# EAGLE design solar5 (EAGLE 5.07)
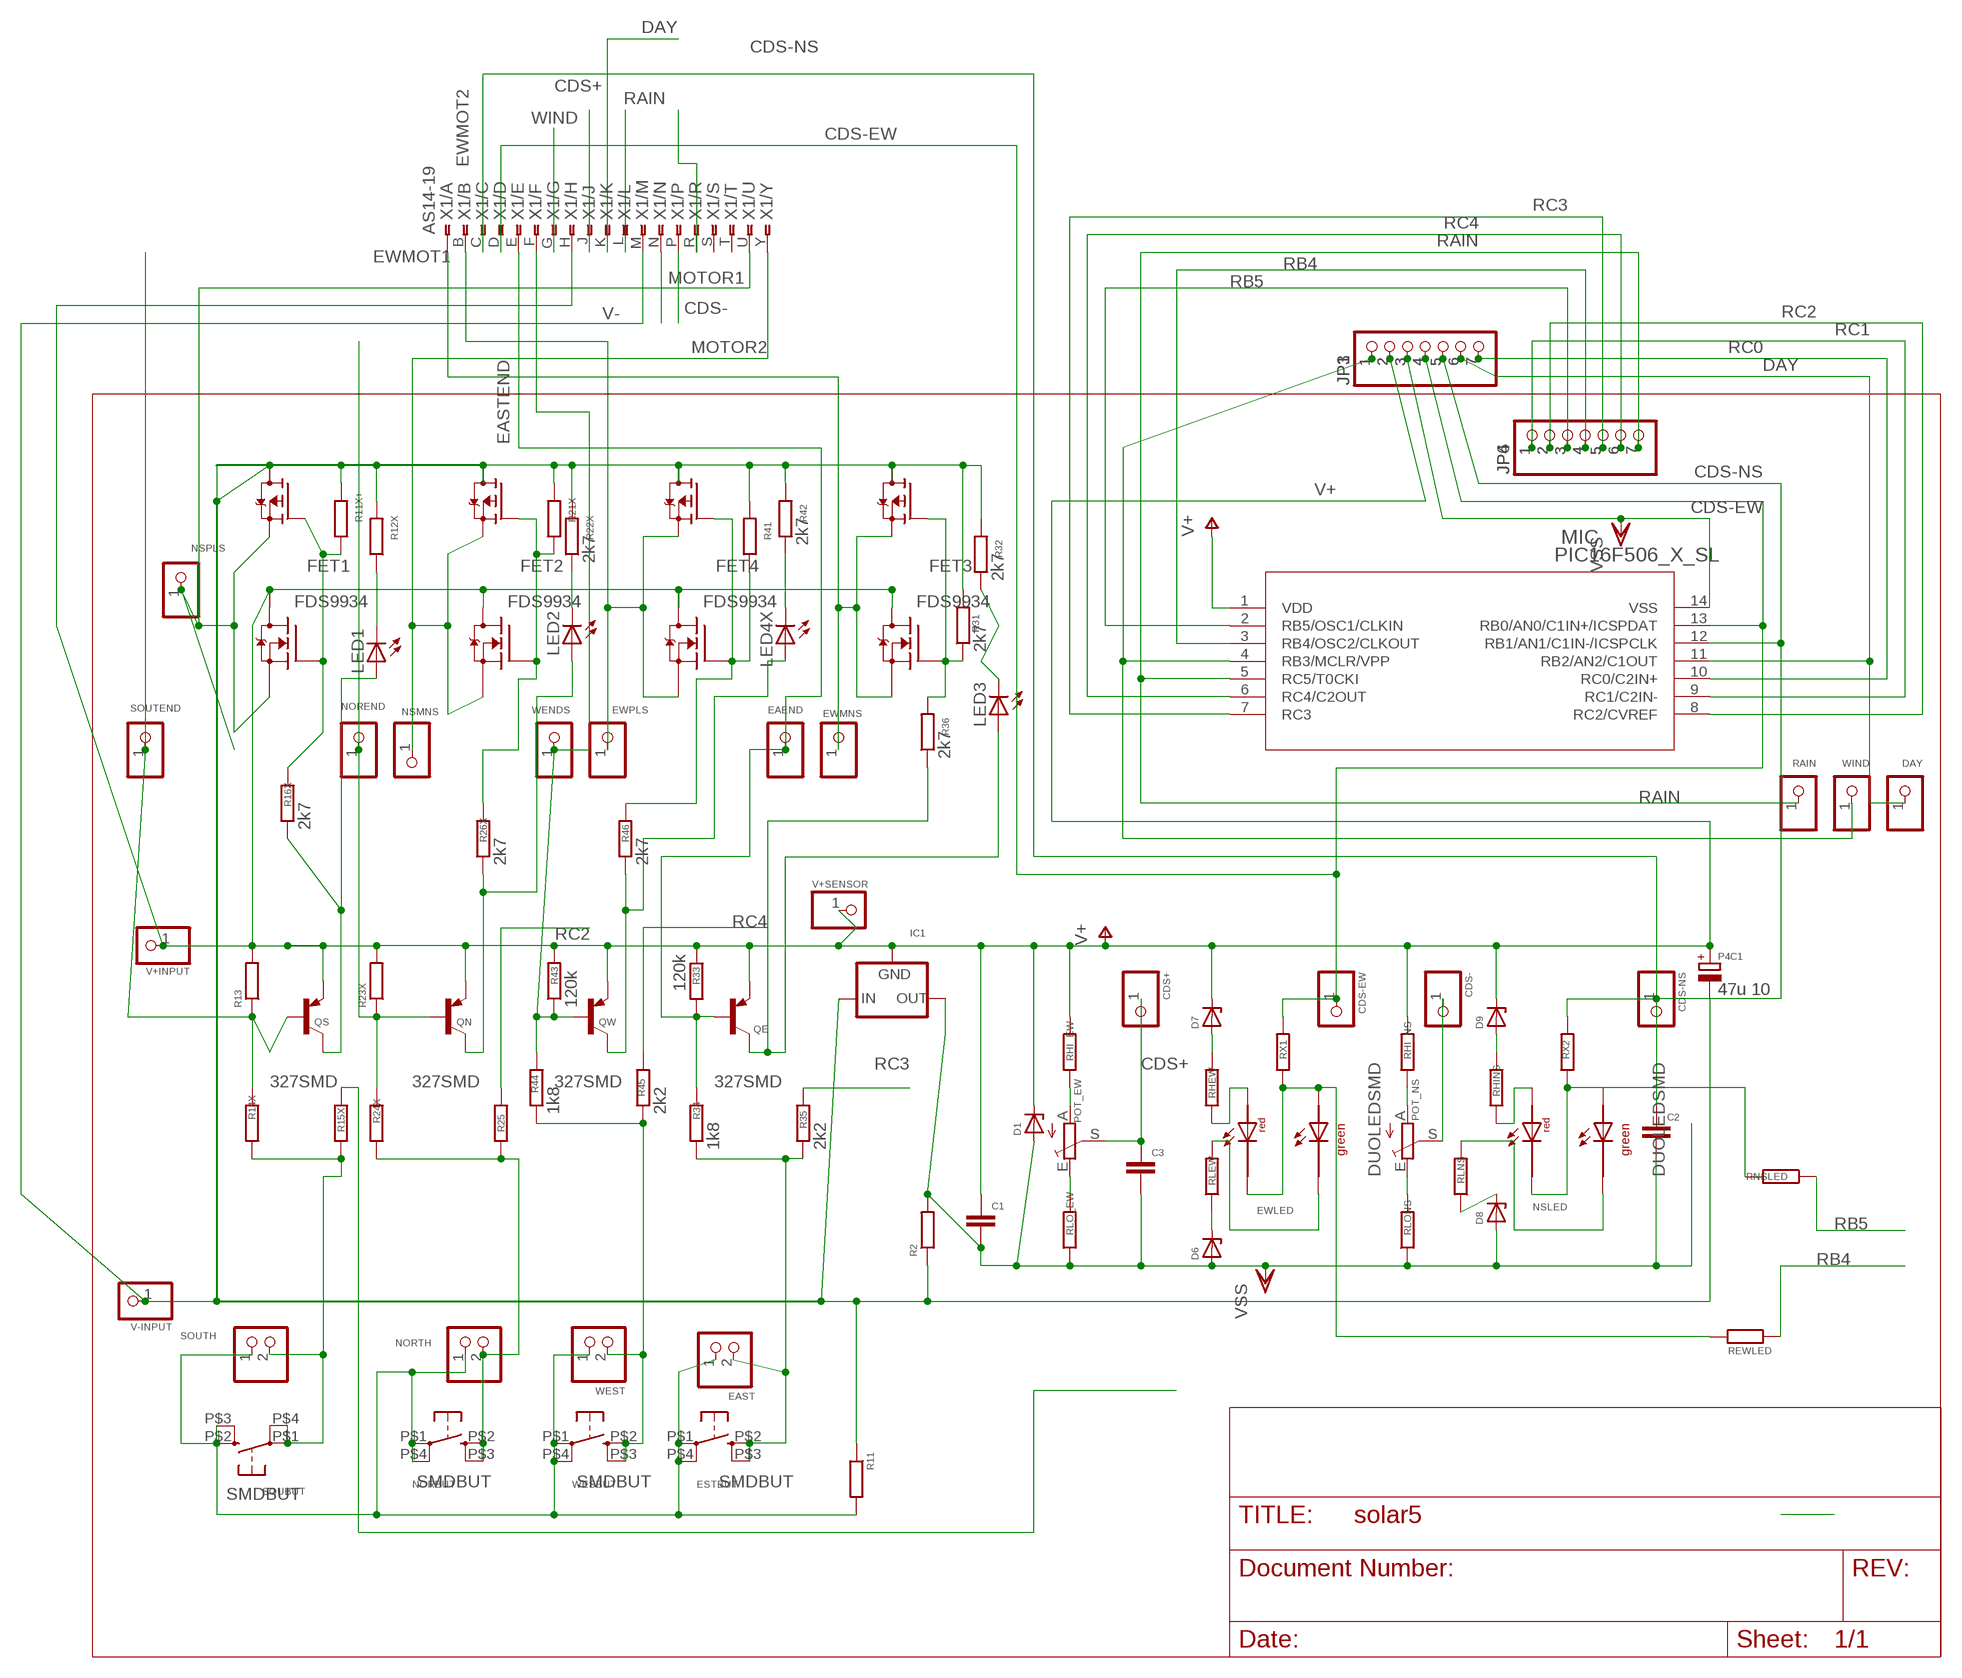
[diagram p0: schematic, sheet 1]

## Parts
C1  C-EUC1206  [C1206]
C2  C-EUC1206  [C1206]
C3  C-EUC1206  [C1206]
CDS+  PINHD-1X1INCH  [1X01]
CDS-  PINHD-1X1INCH  [1X01]
CDS-EW  PINHD-1X1INCH  [1X01]
CDS-NS  PINHD-1X1INCH  [1X01]
D1  ZENER-DIODESOD80C  [SOD80C]
D6  ZENER-DIODESOD80C  [SOD80C]
D7  ZENER-DIODESOD80C  [SOD80C]
D8  ZENER-DIODESOD80C  [SOD80C]
D9  ZENER-DIODESOD80C  [SOD80C]
DAY  PINHD-1X1INCH  [1X01]
EAEND  PINHD-1X1INCH  [1X01]
EAST  PINHD-1X2STR  [1X02]
ESTBUT  SMDBUT  [SMD10/5]
EWLED  DUOLEDSMD  [DUOLEDSMD]
EWMNS  PINHD-1X10MM6  [1X01M]
EWPLS  PINHD-1X10MM6  [1X01M]
FET1  FDS9934  [SO-8]
FET2  FDS9934  [SO-8]
FET3  FDS9934  [SO-8]
FET4  FDS9934  [SO-8]
IC1  79LXX  [79LXX]
JP1  PINHD-1X7  [1X07]
JP3  PINHD-1X7  [1X07]
JP4  PINHD-1X7  [1X07]
JP6  PINHD-1X7  [1X07]
LED1  LEDCHIPLED_1206  [CHIPLED_1206]
LED2  LEDCHIPLED_1206  [CHIPLED_1206]
LED3  LEDCHIPLED_1206  [CHIPLED_1206]
LED4X  LEDCHIPLED_1206  [CHIPLED_1206]
MIC  PIC16F506_X_SL  [SOIC14_N_MC]
NORBUT  SMDBUT  [SMD10/5]
NOREND  PINHD-1X1INCH  [1X01]
NORTH  PINHD-1X2STR  [1X02]
NSLED  DUOLEDSMD  [DUOLEDSMD]
NSMNS  PINHD-1X1INCH  [1X01]
NSPLS  PINHD-1X10MM6  [1X01M]
P4C1  47u 10  CPOL-EUE5-8.5  [E5-8,5]
POT_EW  TRIM_EU-CA6V  [CA6V]
POT_NS  TRIM_EU-CA6V  [CA6V]
QE  327SMD  BC327SMD  [SOT23-BEC]
QN  327SMD  BC327SMD  [SOT23-BEC]
QS  327SMD  BC327SMD  [SOT23-BEC]
QW  327SMD  BC327SMD  [SOT23-BEC]
R2  R-EU_R0805  [R0805]
R11  R-EU_R0805  [R0805]
R11X+  R-EU_R0805  [R0805]
R12X  R-EU_R0805  [R0805]
R13  R-EU_R0805  [R0805]
R14X  R-EU_R1206  [R1206]
R15X  R-EU_R0805  [R0805]
R16X  2k7  R-EU_R0805  [R0805]
R21X  R-EU_R0805  [R0805]
R22X  2k7  R-EU_R0805  [R0805]
R23X  R-EU_R1206  [R1206]
R24X  R-EU_R1206  [R1206]
R25  R-EU_R0805  [R0805]
R26X  2k7  R-EU_R0805  [R0805]
R31  2k7  R-EU_R0805  [R0805]
R32  2k7  R-EU_R0805  [R0805]
R33  120k  R-EU_R0805  [R0805]
R34  1k8  R-EU_R0805  [R0805]
R35  2k2  R-EU_R0805  [R0805]
R36  2k7  R-EU_R0805  [R0805]
R41  R-EU_R0805  [R0805]
R42  2k7  R-EU_R0805  [R0805]
R43  120k  R-EU_R0805  [R0805]
R44  1k8  R-EU_R0805  [R0805]
R45  2k2  R-EU_R0805  [R0805]
R46  2k7  R-EU_R0805  [R0805]
RAIN  PINHD-1X1INCH  [1X01]
REWLED  R-EU_R0805  [R0805]
RHEW  R-EU_R1206  [R1206]
RHI_EW  R-EU_R1206  [R1206]
RHI_NS  R-EU_R1206  [R1206]
RHINS  R-EU_R1206  [R1206]
RLEW  R-EU_R1206  [R1206]
RLNS  R-EU_R1206  [R1206]
RLO_EW  R-EU_R1206  [R1206]
RLONS  R-EU_R0805  [R0805]
RNSLED  R-EU_R0805  [R0805]
RX1  R-EU_R0805  [R0805]
RX2  R-EU_R0805  [R0805]
SOUBUT  SMDBUT  [SMD10/5]
SOUTEND  PINHD-1X1INCH  [1X01]
SOUTH  PINHD-1X2STR  [1X02]
V+INPUT  PINHD-1X1INCH  [1X01]
V+SENSOR  PINHD-1X10MM6  [1X01M]
V-INPUT  PINHD-1X10MM6  [1X01M]
WENDS  PINHD-1X1INCH  [1X01]
WESBUT  SMDBUT  [SMD10/5]
WEST  PINHD-1X2STR  [1X02]
WIND  PINHD-1X1INCH  [1X01]
X1  AS14-19  AS14-19OLIVE  [Y28M-19TK]

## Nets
CDS+: C3.1 CDS+.1 POT_EW.S X1.J
CDS-: CDS-.1 POT_NS.S X1.P
CDS-EW: CDS-EW.1 JP1.4 JP3.4 MIC.13(RB0/AN0/C1IN+/ICSPDAT) RX1.2 X1.D
CDS-NS: C2.1 CDS-NS.1 JP1.5 JP3.5 MIC.12(RB1/AN1/C1IN-/ICSPCLK) RX2.2 X1.C
DAY: DAY.1 JP1.6 JP3.6 MIC.11(RB2/AN2/C1OUT) X1.K
EASTEND: EAEND.1 QE.B R33.2 R34.2 X1.E
EWMOT1: EWMNS.1 FET3.1(Q1S) FET3.3(Q2S) X1.A
EWMOT2: EWPLS.1 FET4.1(Q1S) FET4.3(Q2S) X1.B
MOTOR1: FET1.1(Q1S) FET1.3(Q2S) NSPLS.1 X1.U
MOTOR2: FET2.1(Q1S) FET2.3(Q2S) NSMNS.1 X1.Y
N$1: POT_NS.E RLONS.2
N$2: LED1.A QS.C R16X.1
N$3: LED2.A QN.C R26X.1
N$4: FET2.2(Q1G) FET2.4(Q2G) R21X.1 R26X.2
N$5: LED1.C R12X.1
N$6: EWLED.AGRN EWLED.CRED REWLED.2 RX1.1
N$8: LED2.C R22X.1
N$9: R14X.1 R15X.1 SOUBUT.P$1(P) SOUBUT.P$4(P1) SOUTH.2
N$10: LED4X.A QW.C R46.1
N$11: EAST.2 ESTBUT.P$2(S) ESTBUT.P$3(S1) R34.1 R35.1
N$14: D7.A RHEW.2
N$15: LED4X.C R42.1
N$17: NORBUT.P$2(S) NORBUT.P$3(S1) NORTH.2 R24X.1 R25.1
N$18: POT_NS.A RHI_NS.1
N$21: POT_EW.E RLO_EW.2
N$22: POT_EW.A RHI_EW.1
N$25: EWLED.ARED RHEW.1
N$27: D6.C RLEW.1
N$28: EWLED.CGRN RLEW.2
N$29: EAST.1 ESTBUT.P$1(P) ESTBUT.P$4(P1) NORBUT.P$1(P) NORBUT.P$4(P1) NORTH.1 R11.2 SOUBUT.P$2(S) SOUBUT.P$3(S1) SOUTH.1 WESBUT.P$1(P) WESBUT.P$4(P1) WEST.1
N$30: NSLED.AGRN NSLED.CRED RNSLED.2 RX2.1
N$37: LED3.A QE.C R36.1
N$39: R44.1 R45.1 WESBUT.P$2(S) WESBUT.P$3(S1) WEST.2
N$41: D9.A RHINS.2
N$42: NSLED.ARED RHINS.1
N$43: D8.C RLNS.1
N$44: NSLED.CGRN RLNS.2
N$50: FET1.2(Q1G) FET1.4(Q2G) R11X+.1 R16X.2
N$54: FET4.2(Q1G) FET4.4(Q2G) R41.1 R46.2
N$55: FET3.2(Q1G) FET3.4(Q2G) R31.1 R36.2
N$56: LED3.C R32.1
NOREND: NOREND.1 QN.B R23X.1 R24X.2 X1.N
RAIN: JP4.7 JP6.7 MIC.5(RC5/T0CKI) RAIN.1 X1.L
RB4: JP4.4 JP6.4 MIC.3(RB4/OSC2/CLKOUT) REWLED.1
RB5: JP4.3 JP6.3 MIC.2(RB5/OSC1/CLKIN) RNSLED.1
RC0: JP1.7 JP3.7 MIC.10(RC0/C2IN+)
RC1: JP4.1 JP6.1 MIC.9(RC1/C2IN-) R15X.2
RC2: JP4.2 JP6.2 MIC.8(RC2/CVREF) R25.2
RC3: JP4.5 JP6.5 MIC.7(RC3) R35.2
RC4: JP4.6 JP6.6 MIC.6(RC4/C2OUT) R45.2
SOU_END: QS.B R13.1 R14X.2 SOUTEND.1 X1.R
V+: C1.1 D1.C D7.C D9.C FET1.7(Q1D2) FET1.8(Q1D1) FET2.7(Q1D2) FET2.8(Q1D1) FET3.7(Q1D2) FET3.8(Q1D1) FET4.7(Q1D2) FET4.8(Q1D1) IC1.GND JP1.2 JP3.2 MIC.1(VDD) P4C1.+ QE.E QN.E QS.E QW.E R13.2 R23X.2 R33.1 R43.2 RHI_EW.2 RHI_NS.2 V+INPUT.1 V+SENSOR.1 X1.H
V-: FET1.5(Q2D2) FET1.6(Q2D) FET2.5(Q2D2) FET2.6(Q2D) FET3.5(Q2D2) FET3.6(Q2D) FET4.5(Q2D2) FET4.6(Q2D) IC1.IN P4C1.- R2.1 R11.1 R11X+.2 R12X.2 R21X.2 R22X.2 R31.2 R32.2 R41.2 R42.2 V-INPUT.1 X1.M
VSS: C1.2 C2.2 C3.2 D1.A D6.A D8.A IC1.OUT JP1.3 JP3.3 MIC.14(VSS) R2.2 RLO_EW.1 RLONS.1
WESTEND: QW.B R43.1 R44.2 WENDS.1 X1.F
WIND: JP1.1 JP3.1 MIC.4(RB3/MCLR/VPP) WIND.1 X1.G
Unconnected: X1.S X1.T

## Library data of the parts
C1-C3 = rcl-2:C-EU: CAPACITOR, European symbol
CDS+ CDS- CDS-EW CDS-NS DAY EAEND EWMNS EWPLS NOREND NSMNS NSPLS RAIN SOUTEND V+INPUT V+SENSOR V-INPUT WENDS WIND = pinhead(2):PINHD-1X1: PIN HEADER
D1 D6-D9 = diode-1:ZENER-DIODE: Z-Diode
EAST NORTH SOUTH WEST = pinhead:PINHD-1X2: PIN HEADER
ESTBUT NORBUT SOUBUT WESBUT = switch-omron:SMDBUT
EWLED NSLED = led:DUOLEDSMD
FET1-FET4 = transistor-fet:FDS9934
IC1 = v-reg:79LXX: VOLTAGE REGULATOR
JP1 JP3 JP4 JP6 = pinhead:PINHD-1X7: PIN HEADER
LED1-LED3 LED4X = led:LED: LED
MIC = pic16f506mc:PIC16F506_X_SL
P4C1 = rcl:CPOL-EU: POLARIZED CAPACITOR, European symbol
POT_EW POT_NS = pot:TRIM_EU-: POTENTIOMETER
QE QN QS QW = transistor-pnp:BC327*: PNP Transistror
R2 R11 R11X+ R12X R13 R14X R15X R16X R21X R22X R23X R24X R25 R26X R31-R36 R41-R46 REWLED RHEW RHI_EW RHI_NS RHINS RLEW RLNS RLO_EW RLONS RNSLED RX1 RX2 = rcl-2:R-EU_: RESISTOR, European symbol
X1 = con-deutsch:AS14-19: DEUTSCH Connector

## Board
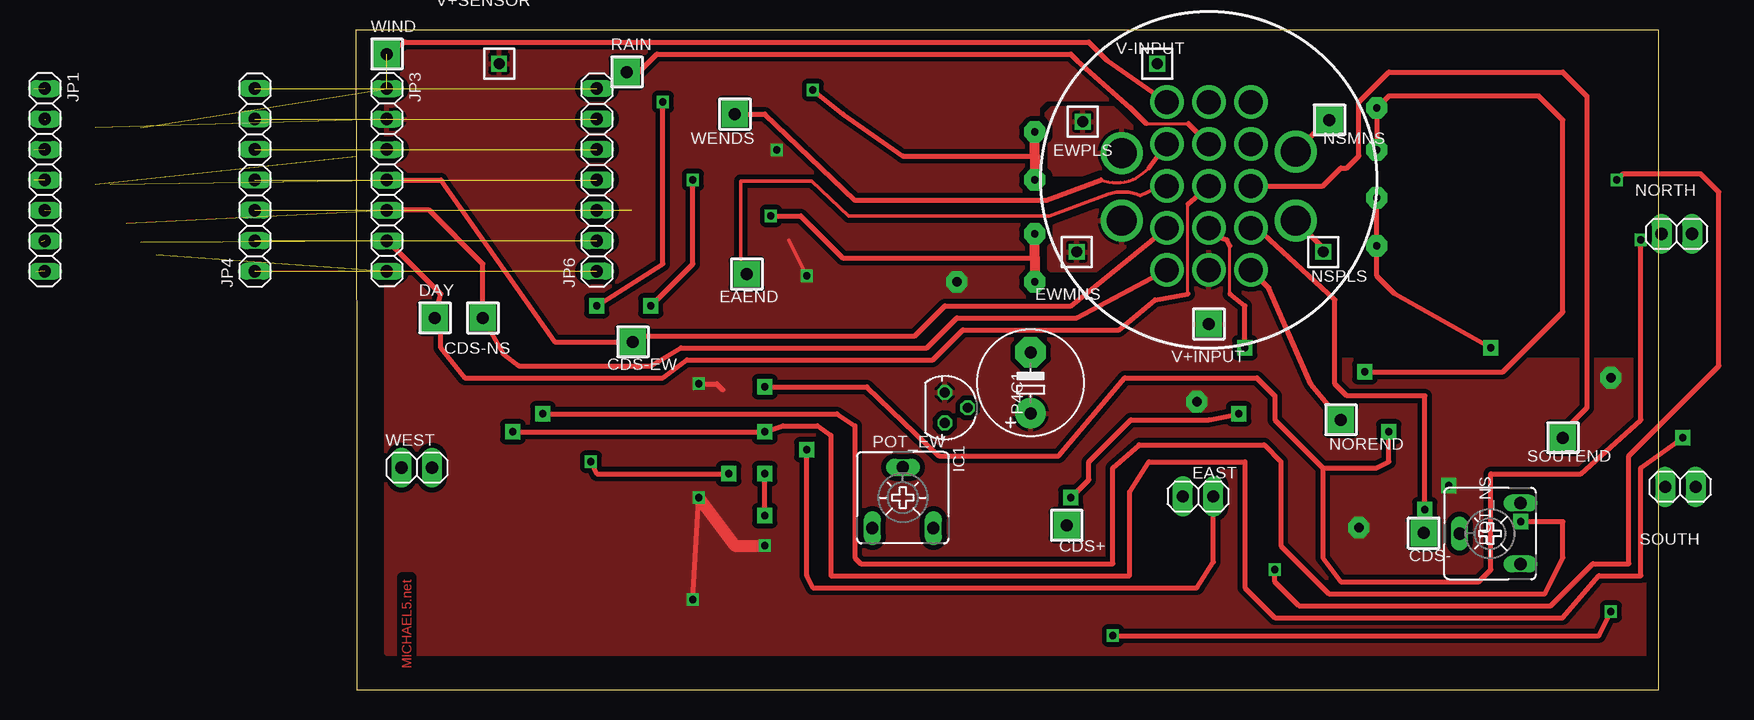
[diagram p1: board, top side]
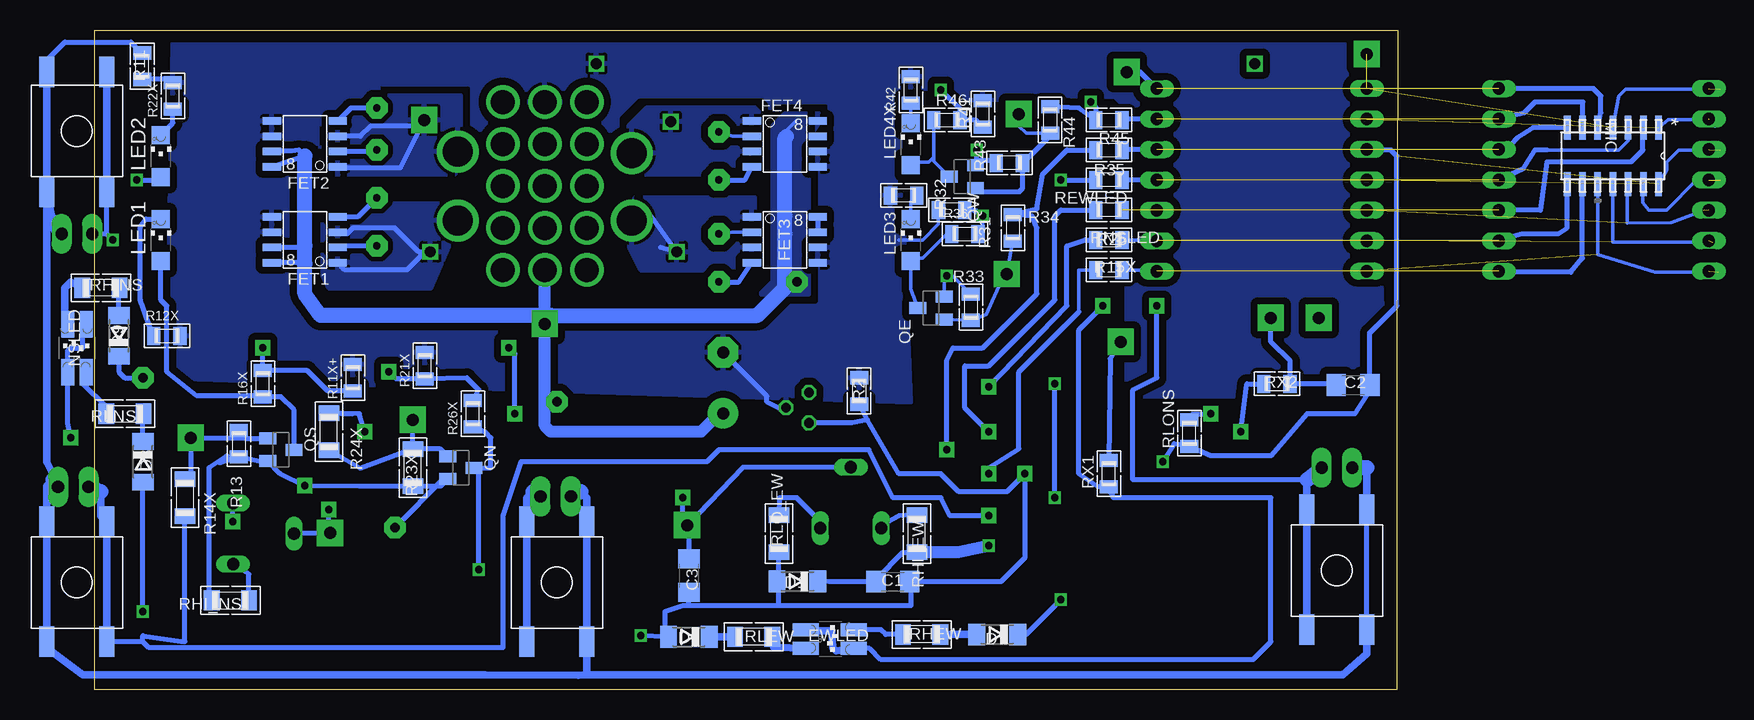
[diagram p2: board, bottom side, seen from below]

Size 108.57 x 55 mm. Coordinates in mm from the lower left corner, seen from the top.
Outline: 0.07,0 108.57,0 108.57,55 0,55 0.07,25 0.07,0
Copper layers (1*16): Top 0.035mm / dielectric 1.5mm / Bottom 0.035mm
Design rules "default *": minimum track width 40mil, minimum drill 30mil, track to track 8mil, track to pad 8mil, pad to pad 8mil, via to via 8mil, smd to smd 8mil, copper to edge 40mil, drill to drill 8mil, minimum pad ring 8mil, minimum via ring 8mil, stop-mask expansion 4mil, vias tented up to drill 0mil, thermal gap 10mil

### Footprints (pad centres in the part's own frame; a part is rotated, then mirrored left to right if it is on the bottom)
C1206 = smd 1.6 x 1.8: 1 -1.4,0; 2 1.4,0
1X01 = drill 1 pad 2.184 square: 1 0,0
SOD80C = smd 1.4 x 1.8: A 1.7,0; C -1.7,0
1X02 = drill 1.016 pad 1.676 long: 1 -1.27,0; 2 1.27,0
SMD10/5 = smd 1.27 x 2.54: P$1 -2.5,0; P$2 2.5,0; P$3 2.5,10; P$4 -2.5,10
DUOLEDSMD = smd 1.067 x 2.184: AGRN 0.77,1.95; ARED -0.77,1.95; CGRN 0.77,-2.05; CRED -0.77,-2.05
1X01M = drill 0.914 square: 1 0,0
SO-8 = smd 1.524 x 0.61: 1 -2.743,1.905; 2 -2.743,0.635; 3 -2.743,-0.635; 4 -2.743,-1.905; 5 2.743,-1.905; 6 2.743,-0.635; 7 2.743,0.635; 8 2.743,1.905
79LXX = drill 0.813 octagon: GND -1.27,0; IN 0,1.905; OUT 1.27,0
1X07 = drill 1.016 long: 1 -7.62,0; 2 -5.08,0; 3 -2.54,0; 4 0,0; 5 2.54,0; 6 5.08,0; 7 7.62,0
CHIPLED_1206 = smd 1.5 x 1.5: A 0,-1.75; C 0,1.75
SOIC14_N_MC = smd 1.981 x 0.559: 1 -2.362,3.81; 2 -2.362,2.54; 3 -2.362,1.27; 4 -2.362,0; 5 -2.362,-1.27; 6 -2.362,-2.54; 7 -2.362,-3.81; 8 2.362,-3.81; 9 2.362,-2.54; 10 2.362,-1.27; 11 2.362,0; 12 2.362,1.27; 13 2.362,2.54; 14 2.362,3.81
E5-8,5 = drill 1 pad 2.54 round: + -2.54,0 | drill 1 pad 2.54 octagon: - 2.54,0
CA6V = drill 1.016 long: A -2.54,-2.54; E 2.54,-2.54; S 0,2.54
SOT23-BEC = smd 1 x 1.4: B -0.95,-1.1; C 0,1.1; E 0.95,-1.1
R0805 = smd 1.1 x 1.5: 1 -1.1,0; 2 1.1,0
R1206 = smd 1.3 x 1.7: 1 -1.55,0; 2 1.55,0
Y28M-19TK = drill 2.5 pad 3.5 round: A -7.25,-2.875; B -7.25,2.75; U 7.25,-2.875; Y 7.25,2.875 | drill 2 pad 2.54 round: C -3.5,-7; D -3.5,-3.5; E -3.5,0; F -3.5,3.5; G -3.5,7; H 0,-7; J 0,-3.5; K 0,0; L 0,3.5; M 0,7; N 3.5,-7; P 3.5,-3.5; R 3.5,0; S 3.5,3.5; T 3.5,7

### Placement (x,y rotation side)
C1  42.07,9 0 bottom
C2  3.72,25.39 0 bottom
C3  59.07,9.5 270 bottom
CDS+  59.22,13.7 0 top
CDS-  88.97,13.05 90 top
CDS-EW  23.07,29 0 top
CDS-NS  10.57,31 90 top
D1  50.02,9.02 180 bottom
D6  59.07,4.4 180 bottom
D7  33.37,4.6 180 bottom
D8  104.57,19 270 bottom
D9  106.57,29.5 90 bottom
DAY  6.57,31 0 top
EAEND  32.57,34.65 90 top
EAST  70.17,16.1 0 top
ESTBUT  70.07,14 180 bottom
EWLED  47.27,4.2 270 bottom
EWMNS  60.07,36.5 90 top
EWPLS  60.57,47.35 90 top
FET1  91.07,37.5 180 bottom
FET2  91.07,45.5 180 bottom
FET3  51.07,37.5 0 bottom
FET4  51.07,45.5 0 bottom
IC1  49.07,23.5 270 top
JP1  not placed on the board
JP3  2.57,42.5 270 top
JP4  -8.43,42.5 90 top  (outside the outline)
JP6  20.07,42.5 90 top
LED1  103.07,37.5 0 bottom
LED2  103.07,44.5 0 bottom
LED3  40.57,37.5 0 bottom
LED4X  40.57,45.5 0 bottom
MIC  -17.93,44.5 270 bottom  (outside the outline)
NORBUT  110.07,41.5 0 bottom
NOREND  82.07,22.5 0 top
NORTH  110.07,38 180 top
NSLED  110.07,28.5 0 bottom
NSMNS  81.12,47.5 0 top
NSPLS  80.62,36.5 0 top
P4C1  56.21,25.58 90 top
POT_EW  45.57,16 0 top
POT_NS  94.51,13.01 90 top
QE  38.9,31.81 90 bottom
QN  78.07,18.5 270 bottom
QS  93.07,20 270 bottom
QW  36.28,42.77 90 bottom
R2  44.89,24.89 270 bottom
R11  104.62,51.98 90 bottom
R11X+  87.07,26 90 bottom
R12X  102.57,29.5 0 bottom
R13  96.57,20.5 270 bottom
R14X  101.07,16 90 bottom
R15X  24.07,35 0 bottom
R16X  94.57,25.5 90 bottom
R21X  81.07,27 90 bottom
R22X  102.07,49.5 90 bottom
R23X  82.07,18.5 270 bottom
R24X  89.07,21.5 270 bottom
R25  24.07,37.5 0 bottom
R26X  77.07,23 90 bottom
R31  37.17,40 180 bottom
R32  41.17,41.2 180 bottom
R33  35.57,31.89 270 bottom
R34  32.07,38.5 270 bottom
R35  24.07,45 0 bottom
R36  36.07,38 0 bottom
R41  34.57,48 90 bottom
R42  40.57,50 90 bottom
R43  32.36,43.91 180 bottom
R44  28.97,47.5 270 bottom
R45  24.07,47.5 0 bottom
R46  37.57,47.5 0 bottom
RAIN  22.57,51.5 0 top
REWLED  24.07,42.5 180 bottom
RHEW  39.67,4.6 0 bottom
RHI_EW  40.07,13 270 bottom
RHI_NS  97.28,7.44 180 bottom
RHINS  108.07,33.5 0 bottom
RLEW  53.67,4.4 0 bottom
RLNS  106.07,23 180 bottom
RLO_EW  51.57,13 90 bottom
RLONS  17.36,21.37 90 bottom
RNSLED  24.07,40 180 bottom
RX1  24.07,18 90 bottom
RX2  10.07,25.5 0 bottom
SOUBUT  110.07,14 180 bottom
SOUTEND  100.57,21 0 top
SOUTH  110.37,16.9 180 top
V+INPUT  71.07,30.5 90 top
V+SENSOR  11.92,52.2 90 top
V-INPUT  66.77,52.2 90 top
WENDS  31.57,48 90 top
WESBUT  5.07,15 180 bottom
WEST  5.07,18.5 0 top
WIND  2.57,53 0 top
X1  71.07,42 0 top

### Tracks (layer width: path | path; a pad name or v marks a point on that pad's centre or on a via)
CDS+  (via drill 0.6 pad 1.27)
  Top 0.254: 72.82,33 72.82,37
  Top 0.406: X1.J 71.07,38 72.57,37.5 72.82,37 | v73.57,23 71.07,22.5 64.57,22.5 61.07,19 61.07,17.5 v59.57,16 | v74.07,28.5 74.07,32 72.82,33
  Bottom 0.406: CDS+.1 54.56,18.54 POT_EW.S | v73.57,23 73.57,28 v74.07,28.5 | v59.57,16 59.57,14.05 CDS+.1 | C3.1 59.07,13.55 CDS+.1
CDS-  (via drill 0.6 pad 1.27)
  Top 0.406: X1.P 75.07,38.5 81.57,32.5 81.57,25.5 82.57,24.5 89.07,24.5 v89.07,15
  Bottom 0.406: 89.42,13.01 POT_NS.S | CDS-.1 89.42,13.01 | v89.07,15 89.07,13.51 89.42,13.01
CDS-EW  (2 unrouted)
  Top 0.406: JP3.4 7.07,42.5 16.57,29 CDS-EW.1 23.56,28.99 24.06,29.51 24.07,29.5 46.57,29.5 49.07,32 59.57,32 X1.D
  Bottom 0.305: MIC.13 -20.43,40.6 -20.93,40 -22.43,40 -24.89,42.46 -26.86,42.46
  Bottom 0.406: RX1.2 23.97,27.6 CDS-EW.1
CDS-NS  (2 unrouted)
  Top 0.406: X1.C 60.07,31 50.07,31 47.57,28.5 27.07,28.5 24.57,27 13.57,27 12.27,28 CDS-NS.1 10.57,35.5 6.11,39.96 JP3.5
  Bottom 0.305: MIC.12 -19.13,41.31 -19.13,38.9 -22.81,38.92 -25.46,39.92
  Bottom 0.406: CDS-NS.1 10.57,29 8.97,27.4 RX2.2 5.22,25.5 C2.1
DAY  (2 unrouted)
  Top 0.254: 69.32,33 69.32,40.5
  Top 0.406: JP3.6 2.99,37 3.07,37 7.07,33 DAY.1 7.07,30.5 7.07,28.5 9.07,26 25.57,26 27.57,27.5 48.07,27.5 50.57,30 63.57,30 66.57,32.5 69.32,33 | 69.32,40.5 X1.K
  Bottom 0.305: MIC.11 -17.93,37.3 -26.24,37.3
EASTEND
  Top 0.305: X1.E 67.07,42 65.37,41.2 arc45 62.37,41.2 57.77,39.5 41.07,39.5 37.97,42.4 32.07,42.4 32.07,35.5 EAEND.1
  Bottom 0.305: QE.B 37.14,30.86 R33.2 34.28,31.29 33.07,34 EAEND.1 R34.2
EWMOT1
  Bottom 0.406: 61.44,36.87 EWMNS.1 62.16,39.41
  pour Bottom (isolate 0.61): 53.57,41 63.57,41 64.07,39.5 64.07,37 63.07,35 54.07,35 53.57,36.5
  pour Top (isolate 0.61): 56.07,39 63.57,41 64.07,39.5 64.07,37 63.07,35 56.57,35 56.07,36.5
EWMOT2
  Bottom 0.406: FET4.1 53.91,47.5
  pour Bottom (isolate 0.61): 54.07,44.5 53.07,48 53.57,48.5 62.57,48.5 64.07,47 64.07,45 63.07,43 54.57,43
  pour Top (isolate 0.61): 57.57,43 57.57,48 58.07,48.5 63.07,48.5 64.57,47 64.57,45 63.57,43
MOTOR1
  Top 0.406: NSPLS.1 80.62,36.83 X1.U
  Bottom 0.406: FET1.3 88.19,38 87.57,38 87.07,38.5 83.57,38.5 81.57,36.5 NSPLS.1 81.07,36.5 82.57,35 87.73,35 FET1.1
  pour Bottom (isolate 0.406): 77.57,40.5 89.57,40.5 89.57,34.5 89.07,33.5 80.57,33.5
MOTOR2
  Top 0.406: NSMNS.1 80.94,47.5 X1.Y
  Bottom 0.406: FET2.1 88.47,43.59 88.57,43.5 83.12,43.5 NSMNS.1 81.62,47 85.57,47 86.43,46.13 FET2.3
  pour Bottom (isolate 0.406): 78.07,49.5 89.07,49.5 89.07,43 78.57,43 78.07,45
N$1  (via drill 0.6 pad 1.27)
  Top 0.406: v15.57,23 40.07,23 41.57,22 41.57,11 42.07,10.5 63.07,10.5 63.07,18.5 65.27,20.4 75.67,20.4 77.07,19 77.07,12 81.07,8 99.07,8 100.57,11 100.57,14 v97.07,14
  Bottom 0.406: RLONS.2 17.1,22.97 v15.57,23 | v97.07,14 97.09,15.5 POT_NS.E
N$2
  Bottom 0.406: LED1.A 103.07,32.5 102.57,32 102.57,26.5 100.07,24.5 94.67,24.5 R16X.1 93.07,24.4 91.97,23.3 QS.C
N$3  (via drill 0.6)
  Top 0.406: v105.07,42.5 105.57,43 112.07,43 113.57,41.5 113.57,27 106.07,19.5 106.07,10.5 103.07,10.5 99.57,7 78.57,7 76.57,9 v76.57,10
  Bottom 0.406: R26X.1 75.97,21.4 75.57,21 75.57,18.5 QN.C 76.57,18.1 v76.57,10 | LED2.A 103.07,42.5 v105.07,42.5
N$4  (via drill 0.6 pad 1.27, 0.6 pad 1.78)
  Top 0.406: v85.07,45 v85.07,48.5 86.07,49.5 98.57,49.5 100.57,47.5 100.57,31.5 95.57,26.5 v84.07,26.5
  Bottom 0.406: FET2.2 85.2,44.87 v85.07,45 | v85.07,48.5 87.23,48.5 FET2.4 | R26X.2 76.57,25 77.57,26 R21X.1 83.47,25.9 v84.07,26.5
N$5
  Bottom 0.406: LED1.C 104.32,39.25 104.77,38.6 104.77,32.5 104.07,30.5 R12X.1
N$6  (via drill 0.6, 0.6 pad 1.27)
  Top 0.406: v24.57,32 28.07,35.5 v28.07,42.5
  Bottom 0.406: EWLED.AGRN 44,3.43 43.07,2.5 12.07,2.5 10.57,4 10.57,16 23.67,16 RX1.1 24.97,16.9 26.57,18 26.57,30 v24.57,32 | v28.07,42.5 REWLED.2
  Bottom 0.61: EWLED.AGRN 46.8,3.23 47.07,3.5 47.17,4.9 48.95,4.9 EWLED.CRED
N$8
  Bottom 0.406: R22X.1 102.07,47.25 LED2.C
N$9  (via drill 0.6 pad 1.27)
  Top 0.406: v34.07,14.5 v34.07,18
  Bottom 0.305: 26.57,31.5 26.57,35 R15X.1
  Bottom 0.406: 26.57,31.5 31.57,26.5 31.57,20.07 34.07,18.5 v34.07,18 | R14X.1 101.07,4 104.57,4.5 104.57,4 | v34.07,14.5 37.32,14.5 38.07,16 42.07,16 44.07,20 56.57,20 57.57,19 73.07,19 74.57,14.5 74.57,3.5 104.07,3.5 104.57,4 | 104.57,4 SOUBUT.P$4
  Bottom 0.61: SOUBUT.P$4 SOUBUT.P$1 108.07,14.5 108.07,16.5
  Bottom 1.27: 108.07,16.5 SOUTH.2
N$10
  Bottom 0.305: 38.67,44.4 R46.1 | 38.67,44.4 39.07,44 40.32,44 LED4X.A | 38.67,44.4 38.67,44.06 QW.C
N$11  (via drill 0.6 pad 1.27)
  Top 0.406: EAST.2 71.44,10.63 70.07,8.5 38.07,8.5 37.57,9.5 v37.57,20
  Bottom 0.406: R35.1 27.57,45 29.57,43 30.07,40.1 R34.1 30.47,39.5 30.07,38.5 30.07,33 34.57,28.5 37.07,28.5 37.57,27.5 v37.57,20
  Bottom 0.61: ESTBUT.P$3 ESTBUT.P$2 72.57,16 72.07,16.5
  Bottom 1.27: EAST.2 72.07,16.5
N$14
  Bottom 0.61: D7.A RHEW.2
N$15
  Bottom 0.305: LED4X.C R42.1
N$17  (via drill 0.6, 0.6 pad 1.27)
  Top 0.406: v34.07,25.25 42.57,25.25 48.57,19.5 58.57,19.5 64.07,26 75.07,26 76.57,24.5 76.57,22.5 80.57,18.5 | 80.57,18.5 85.07,18.5 86.07,19 v86.07,21.5 | v107.07,37.5 107.07,22.5 102.07,18 94.57,18 94.57,10 93.57,9 82.07,9 80.57,11 80.57,18.5
  Bottom 0.406: R25.1 26.07,37.5 27.57,37 27.57,32 v34.07,25.25 | v86.07,21.5 86.52,23 R24X.1 87.12,23 | 107.57,38 NORTH.2 | v107.07,37.5 107.57,38 | 107.57,38 107.57,41
  Bottom 0.61: NORBUT.P$3 NORBUT.P$2 107.57,41
N$18
  Bottom 0.406: RHI_NS.1 95.73,9.64 POT_NS.A
N$21
  Bottom 0.406: POT_EW.E 48.11,14.04 50.07,16 51.52,16 RLO_EW.2
N$22
  Bottom 0.406: RHI_EW.1 40.52,14.55 41.57,14.5 42.57,13.92 POT_EW.A
N$25
  Bottom 0.406: RHEW.1 42.67,4.6 43.07,5 45.29,5 EWLED.ARED
N$27
  Bottom 0.61: RLEW.1 D6.C
N$28
  Bottom 0.61: EWLED.CGRN 51.98,3.53 RLEW.2
N$29
  Bottom 0.406: WESBUT.P$4 WESBUT.P$1 | R11.2 104.65,53.08 105.57,54 111.07,54 112.57,52.5 NORBUT.P$4
  Bottom 0.61: WESBUT.P$1 2.57,18.5 | 67.57,1.25 ESTBUT.P$4 ESTBUT.P$1 67.57,16 68.07,16.5 | 67.57,1.25 4.57,1.25 2.57,3 WESBUT.P$4 | 67.57,1.25 68.27,1.2 76.07,1.23 79.57,1.25 109.57,1.25 112.57,3.5 SOUBUT.P$3 SOUBUT.P$2 112.57,17 112.07,17.5 | SOUTH.1 112.07,18 112.57,19 NORBUT.P$1 | NORBUT.P$1 112.07,39 | NORBUT.P$1 NORBUT.P$4
  Bottom 1.27: 2.57,18.5 WEST.1 | 68.07,16.5 EAST.1 | 112.07,17.5 SOUTH.1 | 112.07,39 NORTH.1
N$30  (via drill 0.6 pad 1.27)
  Top 0.406: v13.07,21.5 v34.07,21.5 35.57,22 38.47,22 39.57,21.2 39.57,9.5 64.47,9.5 64.47,16.5 66.07,19 74.07,19 74.07,8.5 76.57,6 100.57,6 103.57,9.5 107.07,9.5 107.07,18.5 v110.57,21
  Bottom 0.406: NSLED.AGRN 109.57,30.18 109.57,28.5 110.57,28.5 110.84,28.23 NSLED.CRED 110.84,22.23 v110.57,21 | RX2.1 12.57,25.5 v13.07,21.5 | RNSLED.2 28.07,40 28.57,39.5 28.57,32.5 34.07,27 36.07,27 36.07,23.5 v34.07,21.5
N$37
  Bottom 0.305: QE.C 40.57,33.38 LED3.A 40.32,36 39.57,36 37.57,38 R36.1
N$39  (via drill 0.6, 0.6 pad 1.27)
  Top 0.406: v25.57,49 25.57,35.5 v20.07,32
  Bottom 0.406: R44.1 26.57,48.5 R45.1 25.17,48.6 v25.57,49 | v20.07,32 20.07,26 22.07,25 22.07,17.5 7.57,17.5
  Bottom 0.61: WESBUT.P$3 WESBUT.P$2 7.57,17.5
  Bottom 1.27: 7.57,17.5 WEST.2
N$41
  Bottom 0.406: D9.A 106.57,33.45 RHINS.2
N$42
  Bottom 0.61: RHINS.1 110.57,34 111.07,33.5 111.07,30.68 NSLED.ARED
N$43
  Bottom 0.406: D8.C 104.57,22.95 RLNS.1
N$44
  Bottom 0.406: RLNS.2 107.62,23.55 109.57,25.5 109.57,26.18 NSLED.CGRN
N$50  (via drill 0.6 pad 1.27, 0.6 pad 1.78)
  Top 0.406: v85.07,41 v85.07,37 85.07,34.5 86.57,33 v94.57,28.5
  Bottom 0.406: FET1.4 86.66,39.41 v85.07,41 | v85.07,37 88.19,37 FET1.2 | R11X+.1 89.17,24.9 90.87,26.6 R16X.2 v94.57,28.5
N$54  (via drill 0.6, 0.6 pad 1.78)
  Top 0.406: v38.07,50 40.57,48 45.57,44.5 56.57,44.5
  Top 0.813: v56.57,42.5 56.57,44.5 v56.57,46.5
  Bottom 0.305: FET4.2 55.44,46.13 v56.57,46.5
  Bottom 0.406: FET4.4 54.41,42.5 v56.57,42.5 | R41.1 35.17,47.5 R46.2 36.47,48.4 v38.07,50
N$55  (via drill 0.6, 0.6 pad 1.78)
  Top 0.406: v34.57,39.5 37.07,39.5 40.57,36 56.57,36
  Top 0.813: v56.57,34 56.57,36 v56.57,38
  Bottom 0.305: FET3.2 55.44,38.13 v56.57,38 | R31.1 35.07,40 v34.57,39.5 34.57,38.4 R36.2
  Bottom 0.406: FET3.4 54.91,34 v56.57,34 | v34.57,39.5 35.77,40.2
N$56
  Bottom 0.305: LED3.C 40.57,40.7 R32.1
NOREND
  Top 0.406: X1.N 76.07,33.5 79.57,25.5 NOREND.1
  Bottom 0.406: R24X.2 86.47,18.45 R23X.1 | R23X.1 79.77,20.05 QN.B | R23X.1 NOREND.1
RAIN  (1 unrouted)
  Top 0.254: 65.87,47.2 69.37,47.2
  Top 0.406: RAIN.1 23.57,51.5 25.07,53 59.57,53 60.07,52.5 64.57,48.5 65.87,47.2 | 69.37,47.2 X1.L
  Bottom 0.406: JP4.7 -16.31,50.12 -16.93,49.5 -16.93,48.09 MIC.5 | RAIN.1 21.45,51.5 JP6.7
RB4  (1 unrouted)
  Bottom 0.305: MIC.3 -19.2,45.77 -18.43,45 -12.43,45
  Bottom 0.406: -12.43,45 -11.43,45 -10.43,43.4 JP4.4 | JP6.4 REWLED.1
RB5  (2 unrouted)
  Bottom 0.406: JP4.3 -11.89,39.96 -12.43,44 -19.43,44 -20.43,45 -20.43,46.82 MIC.2
RC0  (2 unrouted)
  Bottom 0.305: MIC.10 -16.66,36.27 -21.43,34.8 -26.7,34.8
RC1  (1 unrouted)
  Bottom 0.305: R15X.2 20.69,35 20.57,34.88
  Bottom 0.406: MIC.9 -15.39,35.96 -14.43,34.8 -8.55,34.8 JP4.1 | JP6.1 20.57,34.88 20.9,34.88
RC2  (1 unrouted)
  Bottom 0.305: R25.2 20.15,37.5 JP6.2
  Bottom 0.406: MIC.8 -14.12,38.49 -13.33,38 -10.35,38 JP4.2
RC3  (1 unrouted)
  Bottom 0.406: MIC.7 -11.29,46.86 -9.93,46 -9.47,45.5 JP4.5 | JP6.5 22.93,45.04 R35.2
RC4  (1 unrouted)
  Bottom 0.406: JP4.6 -10.51,48.08 -11.43,49 -15.43,49 -15.43,46.9 MIC.6 | JP6.6 22.89,47.58 R45.2
SOU_END
  Top 0.406: X1.R 80.57,42 82.07,43.5 82.57,43.5 83.57,44.5 83.57,49 86.07,51.5 100.57,51.5 102.57,49.5 102.57,23.5 100.07,21 SOUTEND.1
  Bottom 0.406: 96.47,21 SOUTEND.1 100.57,18.05 R14X.2 | 96.47,21 96.07,21 96.02,20.95 QS.B | 96.47,21 R13.1
V+  (via drill 0.6, 0.6 pad 1.27, 0.8 pad 1.78)  (2 unrouted)
  Top 0.305: v37.57,34.5 36.07,37.5
  Top 0.406: v28.07,7.5 v28.57,16 | v28.57,25.5 30.07,25.5 30.57,25
  Top 1.016: v34.07,12 31.57,12 v28.57,16
  Bottom 0.305: 50.16,47.41 51.07,46.5 51.07,46 | 51.07,39.5 50.98,39.41 | 51.07,38 50.94,38.13 | MIC.1 -22.56,47.54 -25.89,47.54 -26.43,47 -26.46,47 | 37.8,34.27 QE.E | v37.57,34.5 37.07,34.49 R33.1
  Bottom 0.406: FET3.8 FET3.7 | R43.2 33.66,44.11 35.18,44.11 QW.E 35.07,43.84 v35.07,45 | FET2.7 93.55,44.9 92.17,44.9 91.57,45 91.07,44.5 94.07,43.5 93.97,43.59 FET2.8 | FET1.7 91.7,36.87 91.07,37 | FET1.8 91.66,35.59 91.07,35.5 | D1.C 47.34,9 C1.1 43.47,9.2 41.27,11.4 40.12,11.4 RHI_EW.2 | RHI_NS.2 99.07,7.68 99.07,18.5 97.57,19.5 98.17,18.9 R13.2 94.32,18.9 QS.E 93.12,18 v91.07,17 86.52,16.95 R23X.2 79.77,16.95 QN.E 79.52,17.55 v83.57,13.5 | D9.C 106.57,26.5 106.07,26 v104.57,26 | 56.57,23 56.57,23.18 P4C1.+ | D7.C 30.97,4.6 v28.07,7.5 | v28.57,16 v28.57,25.5 | v37.57,34.5 37.8,34.27 | 71.07,24 v70.07,24
  Bottom 1.016: 56.57,23 58.07,21.5 70.57,21.5 71.07,22 71.07,24 V+INPUT.1 X1.H | RHI_EW.2 36.62,11.45 v34.07,12
  Bottom 1.27: V+INPUT.1 70.57,31.2 | 70.57,31.2 53.37,31.2 51.07,33.5 51.07,38 51.07,39.5 51.07,46 50.94,46.13 | 91.07,44.5 91.07,37 91.07,35.5 91.07,33 89.77,31.2 70.57,31.2
  other vias: 50.07,34
  pour Bottom (isolate 0.61): 48.07,48 51.07,48 52.07,47 52.07,34 53.07,33 49.07,33 49.07,46 48.07,47.5
  pour Top (isolate 0.406, rank 2): 2.57,54 70.57,54 78.57,50.5 78.57,27.5 108.07,27.5 108.57,3 2.57,3
V-
  Bottom 0.305: R31.2 38.27,38.8 39.57,37.5 41.57,37.5 | FET3.6 48.19,37
  Bottom 0.406: IC1.IN 51.57,23.5 52.57,24 52.57,24.47 P4C1.- | R11.1 102.35,50.88 R22X.2
  pour Bottom (isolate 0.61, rank 4): 2.07,54 102.07,54 102.57,26 40.57,24 41.57,49 23.57,49.5 23.07,49 22.57,49 22.57,24.5 2.57,24.5 1.07,26
VSS  (via drill 0.6, 0.6 pad 1.27)  (2 unrouted)
  Top 0.406: v63.07,4.5 103.57,4.5 v104.57,6.5 | v31.07,18 20.07,18 v19.57,19
  Bottom 0.305: MIC.14 -22.43,43.33 -22.43,44 -23.43,45 -26.86,45
  Bottom 0.406: JP3.3 2.53,45 0.57,45 0.07,44.5 0.07,32 2.34,29.73 2.34,25.87 C2.2 2.34,24.92 3.57,23 7.57,23 10.57,19.5 15.57,19.5 RLONS.1 18.63,20.5 v19.57,19 | 51.57,9.17 RLO_EW.1 | 51.57,9.17 D1.A | 51.57,7 51.57,9.17 | 51.57,7 40.57,7 40.57,8.6 C1.2 33.07,9 31.07,11 v31.07,18 32.57,16.5 36.57,16.5 38.07,18 41.57,18 44.19,22.5 | IC1.OUT 45.46,22.23 44.19,22.5 | 44.19,22.5 R2.2 | 51.57,7 59.07,7 | 59.07,7 59.57,7 61.07,6.5 61.07,4.7 D6.A 60.97,4.4 v63.07,4.5 | v104.57,6.5 D8.A | 59.07,7 C3.2
WESTEND
  Top 0.254: 62.07,42.5 arc71 66.07,43.5
  Top 0.406: WENDS.1 34.07,48 41.57,40.8 57.57,40.8 62.07,42.5 | 66.07,43.5 X1.F
  Bottom 0.305: R44.2 30.97,46.4 31.57,47 WENDS.1
  Bottom 0.406: R44.2 28.97,46.2 R43.1 31.26,41.81 31.57,41.5 34.85,41.5 QW.B
WIND  (3 unrouted)
  Top 0.406: WIND.1 4.07,54 61.07,54 62.57,52.5 X1.G
  Bottom 0.305: MIC.4 -18.43,49.5 -19.01,50.08 -26.86,50.08

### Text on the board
Top: MICHAEL5.net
